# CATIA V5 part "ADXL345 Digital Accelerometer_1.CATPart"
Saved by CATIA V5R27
Part number: ADXL345 Digital Accelerometer_1
Definition: ADXL345 Digital Accelerometer
Nomenclature: ADXL345 Digital Accelerometer v3
Source: Unknown
Bounding box of the stored display mesh (mm): x -1.869 to 22.261, y -1.59 to 0.02, z -16.866 to 2.184
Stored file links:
  E:\university\my-thesis\My Thesis Publication\Final-Updata\CAD\ADXL345 Digital Accelerometer_1.CATPart
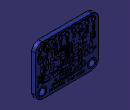
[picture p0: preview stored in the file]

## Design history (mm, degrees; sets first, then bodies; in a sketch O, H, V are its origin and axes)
Set1
  DatumSurface1 "CLOSED_SHELL #65462"
  DatumSurface2 "ADVANCED_FACE #63022"
  DatumSurface3 "ADVANCED_FACE #63029"
  DatumSurface4 "ADVANCED_FACE #63030"
  DatumSurface5 "ADVANCED_FACE #63031"
  DatumSurface6 "ADVANCED_FACE #63032"
  DatumSurface7 "ADVANCED_FACE #63040"
  DatumSurface8 "ADVANCED_FACE #63042"
  DatumSurface9 "ADVANCED_FACE #63089"
  DatumSurface10 "ADVANCED_FACE #63092"
  DatumSurface11 "ADVANCED_FACE #63097"
  DatumSurface12 "ADVANCED_FACE #63098"
  DatumSurface13 "ADVANCED_FACE #63102"
  DatumSurface14 "ADVANCED_FACE #63103"
  DatumSurface15 "ADVANCED_FACE #63110"
  DatumSurface16 "ADVANCED_FACE #63205"
  DatumSurface17 "ADVANCED_FACE #63210"
  DatumSurface18 "ADVANCED_FACE #63217"
  DatumSurface19 "ADVANCED_FACE #63226"
  DatumSurface20 "ADVANCED_FACE #63227"
  DatumSurface21 "ADVANCED_FACE #63228"
  DatumSurface22 "ADVANCED_FACE #63317"
  DatumSurface23 "ADVANCED_FACE #63318"
  DatumSurface24 "ADVANCED_FACE #63356"
  DatumSurface25 "ADVANCED_FACE #63366"
  DatumSurface26 "ADVANCED_FACE #63409"
  DatumSurface27 "ADVANCED_FACE #63415"
  DatumSurface28 "ADVANCED_FACE #63417"
  DatumSurface29 "ADVANCED_FACE #63418"
  DatumSurface30 "ADVANCED_FACE #63419"
  DatumSurface31 "ADVANCED_FACE #63431"
  DatumSurface32 "ADVANCED_FACE #63436"
  DatumSurface33 "ADVANCED_FACE #63577"
  DatumSurface34 "ADVANCED_FACE #63590"
  DatumSurface35 "ADVANCED_FACE #63597"
  DatumSurface36 "ADVANCED_FACE #63598"
  DatumSurface37 "ADVANCED_FACE #63601"
  DatumSurface38 "ADVANCED_FACE #63678"
  DatumSurface39 "ADVANCED_FACE #63686"
  DatumSurface40 "ADVANCED_FACE #63688"
  DatumSurface41 "ADVANCED_FACE #63690"
  DatumSurface42 "ADVANCED_FACE #63825"
  DatumSurface43 "ADVANCED_FACE #63834"
  DatumSurface44 "ADVANCED_FACE #63835"
  DatumSurface45 "ADVANCED_FACE #63947"
  DatumSurface46 "ADVANCED_FACE #63948"
  DatumSurface47 "ADVANCED_FACE #63961"
  DatumSurface48 "ADVANCED_FACE #64003"
  DatumSurface49 "ADVANCED_FACE #64024"
  DatumSurface50 "ADVANCED_FACE #64064"
  DatumSurface51 "ADVANCED_FACE #64082"
  DatumSurface52 "ADVANCED_FACE #64083"
  DatumSurface53 "ADVANCED_FACE #64097"
  DatumSurface54 "ADVANCED_FACE #64113"
  DatumSurface55 "ADVANCED_FACE #64132"
  DatumSurface56 "ADVANCED_FACE #64154"
  DatumSurface57 "ADVANCED_FACE #64174"
  DatumSurface58 "ADVANCED_FACE #64577"
  DatumSurface59 "ADVANCED_FACE #64598"
  DatumSurface60 "ADVANCED_FACE #64655"
  DatumSurface61 "ADVANCED_FACE #64696"
  DatumSurface62 "ADVANCED_FACE #64697"
  DatumSurface63 "ADVANCED_FACE #64702"
  DatumSurface64 "ADVANCED_FACE #64704"
  DatumSurface65 "ADVANCED_FACE #64706"
  DatumSurface66 "ADVANCED_FACE #64707"
  DatumSurface67 "ADVANCED_FACE #64725"
  DatumSurface68 "ADVANCED_FACE #64855"
  DatumSurface69 "ADVANCED_FACE #64856"
  DatumSurface70 "ADVANCED_FACE #64862"
  DatumSurface71 "ADVANCED_FACE #64874"
Set2 "FaceKO#ADVANCED_FACE #63024#63024"
  DatumSurface72 "Sur63024_1"
  DatumCurve1 "Crv63024_1"
  DatumCurve2 "Crv63024_2"
  DatumCurve3 "PCrv63024_3"
  DatumCurve4 "PCrv63024_4"
Set3 "FaceKO#ADVANCED_FACE #63025#63025"
  DatumSurface73 "Sur63025_1"
  DatumCurve5 "Crv63025_1"
  DatumCurve6 "Crv63025_2"
  DatumCurve7 "PCrv63025_3"
  DatumCurve8 "PCrv63025_4"
Set4 "FaceKO#ADVANCED_FACE #63035#63035"
  DatumSurface74 "Sur63035_1"
  DatumCurve9 "Crv63035_1"
  DatumCurve10 "Crv63035_2"
  DatumCurve11 "PCrv63035_3"
  DatumCurve12 "PCrv63035_4"
Set5 "FaceKO#ADVANCED_FACE #63039#63039"
  DatumSurface75 "Sur63039_1"
  DatumCurve13 "Crv63039_1"
  DatumCurve14 "Crv63039_2"
  DatumCurve15 "PCrv63039_3"
  DatumCurve16 "PCrv63039_4"
Set6 "FaceKO#ADVANCED_FACE #63090#63090"
  DatumSurface76 "Sur63090_1"
  DatumCurve17 "Crv63090_1"
  DatumCurve18 "Crv63090_2"
  DatumCurve19 "PCrv63090_3"
  DatumCurve20 "PCrv63090_4"
Set7 "FaceKO#ADVANCED_FACE #63096#63096"
  DatumSurface77 "Sur63096_1"
  DatumCurve21 "Crv63096_1"
  DatumCurve22 "Crv63096_2"
  DatumCurve23 "PCrv63096_3"
  DatumCurve24 "PCrv63096_4"
Set8 "FaceKO#ADVANCED_FACE #63099#63099"
  DatumSurface78 "Sur63099_1"
  DatumCurve25 "Crv63099_1"
  DatumCurve26 "Crv63099_2"
  DatumCurve27 "PCrv63099_3"
  DatumCurve28 "PCrv63099_4"
Set9 "FaceKO#ADVANCED_FACE #63111#63111"
  DatumSurface79 "Sur63111_1"
  DatumCurve29 "Crv63111_1"
  DatumCurve30 "Crv63111_2"
  DatumCurve31 "PCrv63111_3"
  DatumCurve32 "PCrv63111_4"
Set10 "FaceKO#ADVANCED_FACE #63208#63208"
  DatumSurface80 "Sur63208_1"
  DatumCurve33 "Crv63208_1"
  DatumCurve34 "Crv63208_2"
  DatumCurve35 "PCrv63208_3"
  DatumCurve36 "PCrv63208_4"
Set11 "FaceKO#ADVANCED_FACE #63225#63225"
  DatumSurface81 "Sur63225_1"
  DatumCurve37 "Crv63225_1"
  DatumCurve38 "Crv63225_2"
  DatumCurve39 "PCrv63225_3"
  DatumCurve40 "PCrv63225_4"
Set12 "FaceKO#ADVANCED_FACE #63231#63231"
  DatumSurface82 "Sur63231_1"
  DatumCurve41 "Crv63231_1"
  DatumCurve42 "Crv63231_2"
  DatumCurve43 "PCrv63231_3"
  DatumCurve44 "PCrv63231_4"
Set13 "FaceKO#ADVANCED_FACE #63296#63296"
  DatumSurface83 "Sur63296_1"
  DatumCurve45 "Crv63296_1"
  DatumCurve46 "Crv63296_2"
  DatumCurve47 "PCrv63296_3"
  DatumCurve48 "PCrv63296_4"
Set14 "FaceKO#ADVANCED_FACE #63297#63297"
  DatumSurface84 "Sur63297_1"
  DatumCurve49 "Crv63297_1"
  DatumCurve50 "Crv63297_2"
  DatumCurve51 "PCrv63297_3"
  DatumCurve52 "PCrv63297_4"
Set15 "FaceKO#ADVANCED_FACE #63410#63410"
  DatumSurface85 "Sur63410_1"
  DatumCurve53 "Crv63410_1"
  DatumCurve54 "Crv63410_2"
  DatumCurve55 "PCrv63410_3"
  DatumCurve56 "PCrv63410_4"
Set16 "FaceKO#ADVANCED_FACE #63411#63411"
  DatumSurface86 "Sur63411_1"
  DatumCurve57 "Crv63411_1"
  DatumCurve58 "Crv63411_2"
  DatumCurve59 "PCrv63411_3"
  DatumCurve60 "PCrv63411_4"
Set17 "FaceKO#ADVANCED_FACE #63420#63420"
  DatumSurface87 "Sur63420_1"
  DatumCurve61 "Crv63420_1"
  DatumCurve62 "Crv63420_2"
  DatumCurve63 "PCrv63420_3"
  DatumCurve64 "PCrv63420_4"
Set18 "FaceKO#ADVANCED_FACE #63423#63423"
  DatumSurface88 "Sur63423_1"
  DatumCurve65 "Crv63423_1"
  DatumCurve66 "Crv63423_2"
  DatumCurve67 "PCrv63423_3"
  DatumCurve68 "PCrv63423_4"
Set19 "FaceKO#ADVANCED_FACE #63424#63424"
  DatumSurface89 "Sur63424_1"
  DatumCurve69 "Crv63424_1"
  DatumCurve70 "Crv63424_2"
  DatumCurve71 "PCrv63424_3"
  DatumCurve72 "PCrv63424_4"
Set20 "FaceKO#ADVANCED_FACE #63430#63430"
  DatumSurface90 "Sur63430_1"
  DatumCurve73 "Crv63430_1"
  DatumCurve74 "Crv63430_2"
  DatumCurve75 "PCrv63430_3"
  DatumCurve76 "PCrv63430_4"
Set21 "FaceKO#ADVANCED_FACE #63433#63433"
  DatumSurface91 "Sur63433_1"
  DatumCurve77 "Crv63433_1"
  DatumCurve78 "Crv63433_2"
  DatumCurve79 "PCrv63433_3"
  DatumCurve80 "PCrv63433_4"
Set22 "FaceKO#ADVANCED_FACE #63580#63580"
  DatumSurface92 "Sur63580_1"
  DatumCurve81 "Crv63580_1"
  DatumCurve82 "Crv63580_2"
  DatumCurve83 "PCrv63580_3"
  DatumCurve84 "PCrv63580_4"
Set23 "FaceKO#ADVANCED_FACE #63584#63584"
  DatumSurface93 "Sur63584_1"
  DatumCurve85 "Crv63584_1"
  DatumCurve86 "Crv63584_2"
  DatumCurve87 "PCrv63584_3"
  DatumCurve88 "PCrv63584_4"
Set24 "FaceKO#ADVANCED_FACE #63587#63587"
  DatumSurface94 "Sur63587_1"
  DatumCurve89 "Crv63587_1"
  DatumCurve90 "Crv63587_2"
  DatumCurve91 "PCrv63587_3"
  DatumCurve92 "PCrv63587_4"
Set25 "FaceKO#ADVANCED_FACE #63594#63594"
  DatumSurface95 "Sur63594_1"
  DatumCurve93 "Crv63594_1"
  DatumCurve94 "Crv63594_2"
  DatumCurve95 "PCrv63594_3"
  DatumCurve96 "PCrv63594_4"
Set26 "FaceKO#ADVANCED_FACE #63596#63596"
  DatumSurface96 "Sur63596_1"
  DatumCurve97 "Crv63596_1"
  DatumCurve98 "Crv63596_2"
  DatumCurve99 "PCrv63596_3"
  DatumCurve100 "PCrv63596_4"
Set27 "FaceKO#ADVANCED_FACE #63600#63600"
  DatumSurface97 "Sur63600_1"
  DatumCurve101 "Crv63600_1"
  DatumCurve102 "Crv63600_2"
  DatumCurve103 "PCrv63600_3"
  DatumCurve104 "PCrv63600_4"
Set28 "FaceKO#ADVANCED_FACE #63685#63685"
  DatumSurface98 "Sur63685_1"
  DatumCurve105 "Crv63685_1"
  DatumCurve106 "Crv63685_2"
  DatumCurve107 "PCrv63685_3"
  DatumCurve108 "PCrv63685_4"
Set29 "FaceKO#ADVANCED_FACE #63687#63687"
  DatumSurface99 "Sur63687_1"
  DatumCurve109 "Crv63687_1"
  DatumCurve110 "Crv63687_2"
  DatumCurve111 "PCrv63687_3"
  DatumCurve112 "PCrv63687_4"
Set30 "FaceKO#ADVANCED_FACE #63691#63691"
  DatumSurface100 "Sur63691_1"
  DatumCurve113 "Crv63691_1"
  DatumCurve114 "Crv63691_2"
  DatumCurve115 "PCrv63691_3"
  DatumCurve116 "PCrv63691_4"
Set31 "FaceKO#ADVANCED_FACE #63697#63697"
  DatumSurface101 "Sur63697_1"
  DatumCurve117 "Crv63697_1"
  DatumCurve118 "Crv63697_2"
  DatumCurve119 "PCrv63697_3"
  DatumCurve120 "PCrv63697_4"
Set32 "FaceKO#ADVANCED_FACE #63824#63824"
  DatumSurface102 "Sur63824_1"
  DatumCurve121 "Crv63824_1"
  DatumCurve122 "Crv63824_2"
  DatumCurve123 "PCrv63824_3"
  DatumCurve124 "PCrv63824_4"
Set33 "FaceKO#ADVANCED_FACE #63837#63837"
  DatumSurface103 "Sur63837_1"
  DatumCurve125 "Crv63837_1"
  DatumCurve126 "Crv63837_2"
  DatumCurve127 "PCrv63837_3"
  DatumCurve128 "PCrv63837_4"
Set34 "FaceKO#ADVANCED_FACE #63944#63944"
  DatumSurface104 "Sur63944_1"
  DatumCurve129 "Crv63944_1"
  DatumCurve130 "Crv63944_2"
  DatumCurve131 "PCrv63944_3"
  DatumCurve132 "PCrv63944_4"
Set35 "FaceKO#ADVANCED_FACE #63946#63946"
  DatumSurface105 "Sur63946_1"
  DatumCurve133 "Crv63946_1"
  DatumCurve134 "Crv63946_2"
  DatumCurve135 "PCrv63946_3"
  DatumCurve136 "PCrv63946_4"
Set36 "FaceKO#ADVANCED_FACE #63996#63996"
  DatumSurface106 "Sur63996_1"
  DatumCurve137 "Crv63996_1"
  DatumCurve138 "Crv63996_2"
  DatumCurve139 "PCrv63996_3"
  DatumCurve140 "PCrv63996_4"
Set37 "FaceKO#ADVANCED_FACE #64109#64109"
  DatumSurface107 "Sur64109_1"
  DatumCurve141 "Crv64109_1"
  DatumCurve142 "Crv64109_2"
  DatumCurve143 "PCrv64109_3"
  DatumCurve144 "PCrv64109_4"
Set38 "FaceKO#ADVANCED_FACE #64114#64114"
  DatumSurface108 "Sur64114_1"
  DatumCurve145 "Crv64114_1"
  DatumCurve146 "Crv64114_2"
  DatumCurve147 "PCrv64114_3"
  DatumCurve148 "PCrv64114_4"
Set39 "FaceKO#ADVANCED_FACE #64115#64115"
  DatumSurface109 "Sur64115_1"
  DatumCurve149 "Crv64115_1"
  DatumCurve150 "Crv64115_2"
  DatumCurve151 "PCrv64115_3"
  DatumCurve152 "PCrv64115_4"
Set40 "FaceKO#ADVANCED_FACE #64153#64153"
  DatumSurface110 "Sur64153_1"
  DatumCurve153 "Crv64153_1"
  DatumCurve154 "Crv64153_2"
  DatumCurve155 "PCrv64153_3"
  DatumCurve156 "PCrv64153_4"
Set41 "FaceKO#ADVANCED_FACE #64155#64155"
  DatumSurface111 "Sur64155_1"
  DatumCurve157 "Crv64155_1"
  DatumCurve158 "Crv64155_2"
  DatumCurve159 "PCrv64155_3"
  DatumCurve160 "PCrv64155_4"
Set42 "FaceKO#ADVANCED_FACE #64175#64175"
  DatumSurface112 "Sur64175_1"
  DatumCurve161 "Crv64175_1"
  DatumCurve162 "Crv64175_2"
  DatumCurve163 "PCrv64175_3"
  DatumCurve164 "PCrv64175_4"
Set43 "FaceKO#ADVANCED_FACE #64564#64564"
  DatumSurface113 "Sur64564_1"
  DatumCurve165 "Crv64564_1"
  DatumCurve166 "Crv64564_2"
  DatumCurve167 "PCrv64564_3"
  DatumCurve168 "PCrv64564_4"
Set44 "FaceKO#ADVANCED_FACE #64572#64572"
  DatumSurface114 "Sur64572_1"
  DatumCurve169 "Crv64572_1"
  DatumCurve170 "Crv64572_2"
  DatumCurve171 "PCrv64572_3"
  DatumCurve172 "PCrv64572_4"
Set45 "FaceKO#ADVANCED_FACE #64573#64573"
  DatumSurface115 "Sur64573_1"
  DatumCurve173 "Crv64573_1"
  DatumCurve174 "Crv64573_2"
  DatumCurve175 "PCrv64573_3"
  DatumCurve176 "PCrv64573_4"
Set46 "FaceKO#ADVANCED_FACE #64579#64579"
  DatumSurface116 "Sur64579_1"
  DatumCurve177 "Crv64579_1"
  DatumCurve178 "Crv64579_2"
  DatumCurve179 "PCrv64579_3"
  DatumCurve180 "PCrv64579_4"
Set47 "FaceKO#ADVANCED_FACE #64585#64585"
  DatumSurface117 "Sur64585_1"
  DatumCurve181 "Crv64585_1"
  DatumCurve182 "Crv64585_2"
  DatumCurve183 "PCrv64585_3"
  DatumCurve184 "PCrv64585_4"
Set48 "FaceKO#ADVANCED_FACE #64595#64595"
  DatumSurface118 "Sur64595_1"
  DatumCurve185 "Crv64595_1"
  DatumCurve186 "Crv64595_2"
  DatumCurve187 "PCrv64595_3"
  DatumCurve188 "PCrv64595_4"
Set49 "FaceKO#ADVANCED_FACE #64596#64596"
  DatumSurface119 "Sur64596_1"
  DatumCurve189 "Crv64596_1"
  DatumCurve190 "Crv64596_2"
  DatumCurve191 "PCrv64596_3"
  DatumCurve192 "PCrv64596_4"
Set50 "FaceKO#ADVANCED_FACE #64726#64726"
  DatumSurface120 "Sur64726_1"
  DatumCurve193 "Crv64726_1"
  DatumCurve194 "Crv64726_2"
  DatumCurve195 "PCrv64726_3"
  DatumCurve196 "PCrv64726_4"
Body1 (main body)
